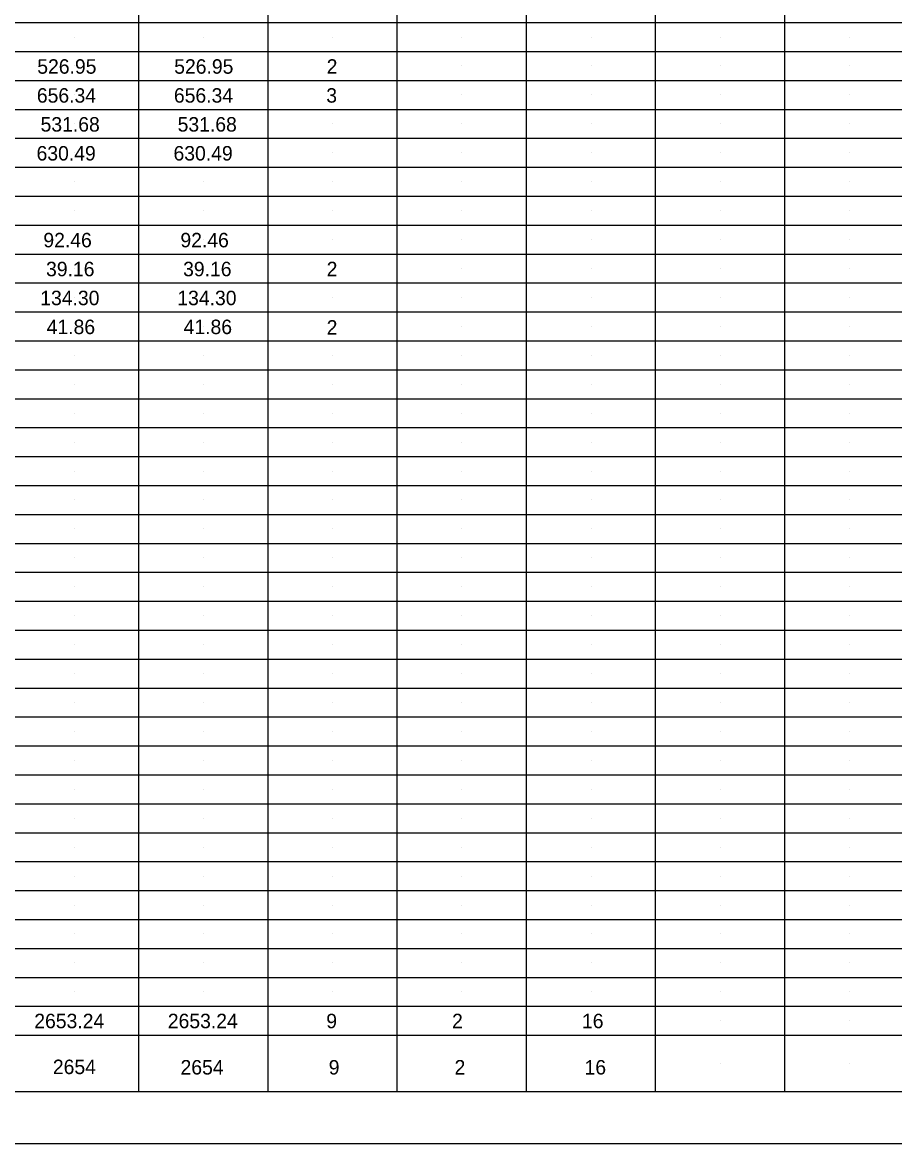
# Model space of a CAD drawing. Extents: x 2073163.9 to 2073197.9, y 634076.5 to 634098.5.
# Drawn here: x 2073181.07 to 2073189.51, y 634076.55 to 634087.4 of the extents above; entities that cross this region are included whole.
import ezdxf

# ---------------------------------------------------------------- set-up
doc = ezdxf.new("R2010")
doc.units = 0
for name, color, linetype in [('SH_Border', 7, 'Continuous'), ('SH_Cut_Line', 7, 'Continuous'), ('SH_Data', 7, 'Continuous'), ('SH_Text', 7, 'Continuous')]:
    doc.layers.add(name, color=color, linetype=linetype)

msp = doc.modelspace()

# ---------------------------------------------------------------- linework, layer by layer
at = {"layer": 'SH_Border'}
msp.add_lwpolyline([(2073165.446, 634098.05), (2073197.446, 634098.05), (2073197.446, 634077.05), (2073165.446, 634077.05)], close=True, dxfattribs=at)
at = {"layer": 'SH_Cut_Line'}
msp.add_lwpolyline([(2073163.946, 634076.55), (2073197.946, 634076.55), (2073197.946, 634098.55), (2073163.946, 634098.55)], close=True, dxfattribs=at)
at = {"layer": 'SH_Data'}
for p, q in [((2073183.446, 634077.05), (2073183.447, 634098.05)), ((2073184.696, 634077.05), (2073184.696, 634098.05)), ((2073187.196, 634077.05), (2073187.196, 634098.05)), ((2073188.446, 634077.05), (2073188.446, 634098.05)), ((2073182.196, 634077.05), (2073182.196, 634097.77)), ((2073185.946, 634077.05), (2073185.946, 634097.77)), ((2073165.446, 634087.398), (2073195.946, 634087.398)), ((2073181.571, 634087.258), (2073181.571, 634087.258)), ((2073182.821, 634087.258), (2073182.821, 634087.258)), ((2073184.071, 634087.258), (2073184.071, 634087.258)), ((2073185.321, 634087.258), (2073185.321, 634087.258)), ((2073186.571, 634087.258), (2073186.571, 634087.258)), ((2073187.821, 634087.258), (2073187.821, 634087.258)), ((2073189.071, 634087.258), (2073189.071, 634087.258)), ((2073165.446, 634087.118), (2073195.946, 634087.118)), ((2073181.571, 634086.978), (2073181.571, 634086.978)), ((2073182.821, 634086.978), (2073182.821, 634086.978)), ((2073184.071, 634086.978), (2073184.071, 634086.978)), ((2073185.321, 634086.978), (2073185.321, 634086.978)), ((2073186.571, 634086.978), (2073186.571, 634086.978)), ((2073187.821, 634086.978), (2073187.821, 634086.978)), ((2073189.071, 634086.978), (2073189.071, 634086.978)), ((2073165.446, 634086.838), (2073195.946, 634086.838)), ((2073181.571, 634086.698), (2073181.571, 634086.698)), ((2073182.821, 634086.698), (2073182.821, 634086.698)), ((2073184.071, 634086.698), (2073184.071, 634086.698)), ((2073185.321, 634086.698), (2073185.321, 634086.698)), ((2073186.571, 634086.698), (2073186.571, 634086.698)), ((2073187.821, 634086.698), (2073187.821, 634086.698)), ((2073189.071, 634086.698), (2073189.071, 634086.698)), ((2073165.446, 634086.558), (2073195.946, 634086.558)), ((2073181.571, 634086.418), (2073181.571, 634086.418)), ((2073182.821, 634086.418), (2073182.821, 634086.418)), ((2073184.071, 634086.418), (2073184.071, 634086.418)), ((2073185.321, 634086.418), (2073185.321, 634086.418)), ((2073186.571, 634086.418), (2073186.571, 634086.418)), ((2073187.821, 634086.418), (2073187.821, 634086.418)), ((2073189.071, 634086.418), (2073189.071, 634086.418)), ((2073165.446, 634086.278), (2073195.946, 634086.278)), ((2073181.571, 634086.138), (2073181.571, 634086.138)), ((2073182.821, 634086.138), (2073182.821, 634086.138)), ((2073184.071, 634086.138), (2073184.071, 634086.138)), ((2073185.321, 634086.138), (2073185.321, 634086.138)), ((2073186.571, 634086.138), (2073186.571, 634086.138)), ((2073187.821, 634086.138), (2073187.821, 634086.138)), ((2073189.071, 634086.138), (2073189.071, 634086.138)), ((2073165.446, 634085.998), (2073195.946, 634085.998)), ((2073181.571, 634085.858), (2073181.571, 634085.858)), ((2073182.821, 634085.858), (2073182.821, 634085.858)), ((2073184.071, 634085.858), (2073184.071, 634085.858)), ((2073185.321, 634085.858), (2073185.321, 634085.858)), ((2073186.571, 634085.858), (2073186.571, 634085.858)), ((2073187.821, 634085.858), (2073187.821, 634085.858)), ((2073189.071, 634085.858), (2073189.071, 634085.858)), ((2073165.446, 634085.718), (2073195.946, 634085.718)), ((2073181.571, 634085.578), (2073181.571, 634085.578)), ((2073182.821, 634085.578), (2073182.821, 634085.578)), ((2073184.071, 634085.578), (2073184.071, 634085.578)), ((2073185.321, 634085.578), (2073185.321, 634085.578)), ((2073186.571, 634085.578), (2073186.571, 634085.578)), ((2073187.821, 634085.578), (2073187.821, 634085.578)), ((2073189.071, 634085.578), (2073189.071, 634085.578)), ((2073165.446, 634085.438), (2073195.946, 634085.438)), ((2073181.571, 634085.298), (2073181.571, 634085.298)), ((2073182.821, 634085.298), (2073182.821, 634085.298)), ((2073184.071, 634085.298), (2073184.071, 634085.298)), ((2073185.321, 634085.298), (2073185.321, 634085.298)), ((2073186.571, 634085.298), (2073186.571, 634085.298)), ((2073187.821, 634085.298), (2073187.821, 634085.298)), ((2073189.071, 634085.298), (2073189.071, 634085.298)), ((2073165.446, 634085.158), (2073195.946, 634085.158)), ((2073181.571, 634085.018), (2073181.571, 634085.018)), ((2073182.821, 634085.018), (2073182.821, 634085.018)), ((2073184.071, 634085.018), (2073184.071, 634085.018)), ((2073185.321, 634085.018), (2073185.321, 634085.018)), ((2073186.571, 634085.018), (2073186.571, 634085.018)), ((2073187.821, 634085.018), (2073187.821, 634085.018)), ((2073189.071, 634085.018), (2073189.071, 634085.018)), ((2073165.446, 634084.878), (2073195.946, 634084.878)), ((2073181.571, 634084.738), (2073181.571, 634084.738)), ((2073182.821, 634084.738), (2073182.821, 634084.738)), ((2073184.071, 634084.738), (2073184.071, 634084.738)), ((2073185.321, 634084.738), (2073185.321, 634084.738)), ((2073186.571, 634084.738), (2073186.571, 634084.738)), ((2073187.821, 634084.738), (2073187.821, 634084.738)), ((2073189.071, 634084.738), (2073189.071, 634084.738)), ((2073165.446, 634084.598), (2073195.946, 634084.598)), ((2073181.571, 634084.458), (2073181.571, 634084.458)), ((2073182.821, 634084.458), (2073182.821, 634084.458)), ((2073184.071, 634084.458), (2073184.071, 634084.458)), ((2073185.321, 634084.458), (2073185.321, 634084.458)), ((2073186.571, 634084.458), (2073186.571, 634084.458)), ((2073187.821, 634084.458), (2073187.821, 634084.458)), ((2073189.071, 634084.458), (2073189.071, 634084.458)), ((2073165.446, 634084.318), (2073195.946, 634084.318)), ((2073181.571, 634084.178), (2073181.571, 634084.178)), ((2073182.821, 634084.178), (2073182.821, 634084.178)), ((2073184.071, 634084.178), (2073184.071, 634084.178)), ((2073185.321, 634084.178), (2073185.321, 634084.178)), ((2073186.571, 634084.178), (2073186.571, 634084.178)), ((2073187.821, 634084.178), (2073187.821, 634084.178)), ((2073189.071, 634084.178), (2073189.071, 634084.178)), ((2073165.446, 634084.038), (2073195.946, 634084.038)), ((2073181.571, 634083.898), (2073181.571, 634083.898)), ((2073182.821, 634083.898), (2073182.821, 634083.898)), ((2073184.071, 634083.898), (2073184.071, 634083.898)), ((2073185.321, 634083.898), (2073185.321, 634083.898)), ((2073186.571, 634083.898), (2073186.571, 634083.898)), ((2073187.821, 634083.898), (2073187.821, 634083.898)), ((2073189.071, 634083.898), (2073189.071, 634083.898)), ((2073165.446, 634083.758), (2073195.946, 634083.758)), ((2073181.571, 634083.618), (2073181.571, 634083.618)), ((2073182.821, 634083.618), (2073182.821, 634083.618)), ((2073184.071, 634083.618), (2073184.071, 634083.618)), ((2073185.321, 634083.618), (2073185.321, 634083.618)), ((2073186.571, 634083.618), (2073186.571, 634083.618)), ((2073187.821, 634083.618), (2073187.821, 634083.618)), ((2073189.071, 634083.618), (2073189.071, 634083.618)), ((2073165.446, 634083.478), (2073195.946, 634083.478)), ((2073181.571, 634083.338), (2073181.571, 634083.338)), ((2073182.821, 634083.338), (2073182.821, 634083.338)), ((2073184.071, 634083.338), (2073184.071, 634083.338)), ((2073185.321, 634083.338), (2073185.321, 634083.338)), ((2073186.571, 634083.338), (2073186.571, 634083.338)), ((2073187.821, 634083.338), (2073187.821, 634083.338)), ((2073189.071, 634083.338), (2073189.071, 634083.338)), ((2073165.446, 634083.198), (2073195.946, 634083.198)), ((2073181.571, 634083.058), (2073181.571, 634083.058)), ((2073182.821, 634083.058), (2073182.821, 634083.058)), ((2073184.071, 634083.058), (2073184.071, 634083.058)), ((2073185.321, 634083.058), (2073185.321, 634083.058)), ((2073186.571, 634083.058), (2073186.571, 634083.058)), ((2073187.821, 634083.058), (2073187.821, 634083.058)), ((2073189.071, 634083.058), (2073189.071, 634083.058)), ((2073165.446, 634082.918), (2073195.946, 634082.918)), ((2073181.571, 634082.778), (2073181.571, 634082.778)), ((2073182.821, 634082.778), (2073182.821, 634082.778)), ((2073184.071, 634082.778), (2073184.071, 634082.778)), ((2073185.321, 634082.778), (2073185.321, 634082.778)), ((2073186.571, 634082.778), (2073186.571, 634082.778)), ((2073187.821, 634082.778), (2073187.821, 634082.778)), ((2073189.071, 634082.778), (2073189.071, 634082.778)), ((2073165.446, 634082.638), (2073195.946, 634082.638)), ((2073181.571, 634082.498), (2073181.571, 634082.498)), ((2073182.821, 634082.498), (2073182.821, 634082.498)), ((2073184.071, 634082.498), (2073184.071, 634082.498)), ((2073185.321, 634082.498), (2073185.321, 634082.498)), ((2073186.571, 634082.498), (2073186.571, 634082.498)), ((2073187.821, 634082.498), (2073187.821, 634082.498)), ((2073189.071, 634082.498), (2073189.071, 634082.498)), ((2073165.446, 634082.358), (2073195.946, 634082.358)), ((2073181.571, 634082.218), (2073181.571, 634082.218)), ((2073182.821, 634082.218), (2073182.821, 634082.218)), ((2073184.071, 634082.218), (2073184.071, 634082.218)), ((2073185.321, 634082.218), (2073185.321, 634082.218)), ((2073186.571, 634082.218), (2073186.571, 634082.218)), ((2073187.821, 634082.218), (2073187.821, 634082.218)), ((2073189.071, 634082.218), (2073189.071, 634082.218)), ((2073165.446, 634082.078), (2073195.946, 634082.078)), ((2073181.571, 634081.938), (2073181.571, 634081.938)), ((2073182.821, 634081.938), (2073182.821, 634081.938)), ((2073184.071, 634081.938), (2073184.071, 634081.938)), ((2073185.321, 634081.938), (2073185.321, 634081.938)), ((2073186.571, 634081.938), (2073186.571, 634081.938)), ((2073187.821, 634081.938), (2073187.821, 634081.938)), ((2073189.071, 634081.938), (2073189.071, 634081.938)), ((2073165.446, 634081.798), (2073195.946, 634081.798)), ((2073181.571, 634081.658), (2073181.571, 634081.658)), ((2073182.821, 634081.658), (2073182.821, 634081.658)), ((2073184.071, 634081.658), (2073184.071, 634081.658)), ((2073185.321, 634081.658), (2073185.321, 634081.658)), ((2073186.571, 634081.658), (2073186.571, 634081.658)), ((2073187.821, 634081.658), (2073187.821, 634081.658)), ((2073189.071, 634081.658), (2073189.071, 634081.658)), ((2073165.446, 634081.518), (2073195.946, 634081.518)), ((2073181.571, 634081.378), (2073181.571, 634081.378)), ((2073182.821, 634081.378), (2073182.821, 634081.378)), ((2073184.071, 634081.378), (2073184.071, 634081.378)), ((2073185.321, 634081.378), (2073185.321, 634081.378)), ((2073186.571, 634081.378), (2073186.571, 634081.378)), ((2073187.821, 634081.378), (2073187.821, 634081.378)), ((2073189.071, 634081.378), (2073189.071, 634081.378)), ((2073165.446, 634081.238), (2073195.946, 634081.238)), ((2073181.571, 634081.098), (2073181.571, 634081.098)), ((2073182.821, 634081.098), (2073182.821, 634081.098)), ((2073184.071, 634081.098), (2073184.071, 634081.098)), ((2073185.321, 634081.098), (2073185.321, 634081.098)), ((2073186.571, 634081.098), (2073186.571, 634081.098)), ((2073187.821, 634081.098), (2073187.821, 634081.098)), ((2073189.071, 634081.098), (2073189.071, 634081.098)), ((2073165.446, 634080.958), (2073195.946, 634080.958)), ((2073181.571, 634080.818), (2073181.571, 634080.818)), ((2073182.821, 634080.818), (2073182.821, 634080.818)), ((2073184.071, 634080.818), (2073184.071, 634080.818)), ((2073185.321, 634080.818), (2073185.321, 634080.818)), ((2073186.571, 634080.818), (2073186.571, 634080.818)), ((2073187.821, 634080.818), (2073187.821, 634080.818)), ((2073189.071, 634080.818), (2073189.071, 634080.818)), ((2073165.446, 634080.678), (2073195.946, 634080.678)), ((2073181.571, 634080.538), (2073181.571, 634080.538)), ((2073182.821, 634080.538), (2073182.821, 634080.538)), ((2073184.071, 634080.538), (2073184.071, 634080.538)), ((2073185.321, 634080.538), (2073185.321, 634080.538)), ((2073186.571, 634080.538), (2073186.571, 634080.538)), ((2073187.821, 634080.538), (2073187.821, 634080.538)), ((2073189.071, 634080.538), (2073189.071, 634080.538)), ((2073165.446, 634080.398), (2073195.946, 634080.398)), ((2073181.571, 634080.258), (2073181.571, 634080.258)), ((2073182.821, 634080.258), (2073182.821, 634080.258)), ((2073184.071, 634080.258), (2073184.071, 634080.258)), ((2073185.321, 634080.258), (2073185.321, 634080.258)), ((2073186.571, 634080.258), (2073186.571, 634080.258)), ((2073187.821, 634080.258), (2073187.821, 634080.258)), ((2073189.071, 634080.258), (2073189.071, 634080.258)), ((2073165.446, 634080.118), (2073195.946, 634080.118)), ((2073181.571, 634079.978), (2073181.571, 634079.978)), ((2073182.821, 634079.978), (2073182.821, 634079.978)), ((2073184.071, 634079.978), (2073184.071, 634079.978)), ((2073185.321, 634079.978), (2073185.321, 634079.978)), ((2073186.571, 634079.978), (2073186.571, 634079.978)), ((2073187.821, 634079.978), (2073187.821, 634079.978)), ((2073189.071, 634079.978), (2073189.071, 634079.978)), ((2073165.446, 634079.838), (2073195.946, 634079.838)), ((2073181.571, 634079.698), (2073181.571, 634079.698)), ((2073182.821, 634079.698), (2073182.821, 634079.698)), ((2073184.071, 634079.698), (2073184.071, 634079.698)), ((2073185.321, 634079.698), (2073185.321, 634079.698)), ((2073186.571, 634079.698), (2073186.571, 634079.698)), ((2073187.821, 634079.698), (2073187.821, 634079.698)), ((2073189.071, 634079.698), (2073189.071, 634079.698)), ((2073165.446, 634079.558), (2073195.946, 634079.558)), ((2073181.571, 634079.418), (2073181.571, 634079.418)), ((2073182.821, 634079.418), (2073182.821, 634079.418)), ((2073184.071, 634079.418), (2073184.071, 634079.418)), ((2073185.321, 634079.418), (2073185.321, 634079.418)), ((2073186.571, 634079.418), (2073186.571, 634079.418)), ((2073187.821, 634079.418), (2073187.821, 634079.418)), ((2073189.071, 634079.418), (2073189.071, 634079.418)), ((2073165.446, 634079.278), (2073195.946, 634079.278)), ((2073181.571, 634079.138), (2073181.571, 634079.138)), ((2073182.821, 634079.138), (2073182.821, 634079.138)), ((2073184.071, 634079.138), (2073184.071, 634079.138)), ((2073185.321, 634079.138), (2073185.321, 634079.138)), ((2073186.571, 634079.138), (2073186.571, 634079.138)), ((2073187.821, 634079.138), (2073187.821, 634079.138)), ((2073189.071, 634079.138), (2073189.071, 634079.138)), ((2073165.446, 634078.998), (2073195.946, 634078.998)), ((2073181.571, 634078.858), (2073181.571, 634078.858)), ((2073182.821, 634078.858), (2073182.821, 634078.858)), ((2073184.071, 634078.858), (2073184.071, 634078.858)), ((2073185.321, 634078.858), (2073185.321, 634078.858)), ((2073186.571, 634078.858), (2073186.571, 634078.858)), ((2073187.821, 634078.858), (2073187.821, 634078.858)), ((2073189.071, 634078.858), (2073189.071, 634078.858)), ((2073165.446, 634078.718), (2073195.946, 634078.718)), ((2073181.571, 634078.578), (2073181.571, 634078.578)), ((2073182.821, 634078.578), (2073182.821, 634078.578)), ((2073184.071, 634078.578), (2073184.071, 634078.578)), ((2073185.321, 634078.578), (2073185.321, 634078.578)), ((2073186.571, 634078.578), (2073186.571, 634078.578)), ((2073187.821, 634078.578), (2073187.821, 634078.578)), ((2073189.071, 634078.578), (2073189.071, 634078.578)), ((2073165.446, 634078.438), (2073195.946, 634078.438)), ((2073181.571, 634078.298), (2073181.571, 634078.298)), ((2073182.821, 634078.298), (2073182.821, 634078.298)), ((2073184.071, 634078.298), (2073184.071, 634078.298)), ((2073185.321, 634078.298), (2073185.321, 634078.298)), ((2073186.571, 634078.298), (2073186.571, 634078.298)), ((2073187.821, 634078.298), (2073187.821, 634078.298)), ((2073189.071, 634078.298), (2073189.071, 634078.298)), ((2073165.446, 634078.158), (2073195.946, 634078.158)), ((2073181.571, 634078.018), (2073181.571, 634078.018)), ((2073182.821, 634078.018), (2073182.821, 634078.018)), ((2073184.071, 634078.018), (2073184.071, 634078.018)), ((2073185.321, 634078.018), (2073185.321, 634078.018)), ((2073186.571, 634078.018), (2073186.571, 634078.018)), ((2073187.821, 634078.018), (2073187.821, 634078.018)), ((2073189.071, 634078.018), (2073189.071, 634078.018)), ((2073165.446, 634077.878), (2073195.946, 634077.878)), ((2073181.571, 634077.738), (2073181.571, 634077.738)), ((2073182.821, 634077.738), (2073182.821, 634077.738)), ((2073184.071, 634077.738), (2073184.071, 634077.738)), ((2073185.321, 634077.738), (2073185.321, 634077.738)), ((2073186.571, 634077.738), (2073186.571, 634077.738)), ((2073187.821, 634077.738), (2073187.821, 634077.738)), ((2073189.071, 634077.738), (2073189.071, 634077.738)), ((2073165.446, 634077.598), (2073195.946, 634077.598)), ((2073181.571, 634077.324), (2073181.571, 634077.324)), ((2073182.821, 634077.324), (2073182.821, 634077.324)), ((2073184.071, 634077.324), (2073184.071, 634077.324)), ((2073185.321, 634077.324), (2073185.321, 634077.324)), ((2073186.571, 634077.324), (2073186.571, 634077.324)), ((2073187.821, 634077.324), (2073187.821, 634077.324)), ((2073189.071, 634077.324), (2073189.071, 634077.324))]:
    msp.add_line(p, q, dxfattribs=at)

# ---------------------------------------------------------------- texts
at = {"layer": 'SH_Text'}
for s, p in [('526.95', (2073181.213, 634086.903)), ('526.95', (2073182.538, 634086.903)), ('2', (2073184.013, 634086.903)), ('656.34', (2073181.209, 634086.623)), ('656.34', (2073182.535, 634086.623)), ('3', (2073184.009, 634086.623)), ('531.68', (2073181.245, 634086.343)), ('531.68', (2073182.571, 634086.343)), ('630.49', (2073181.206, 634086.063)), ('630.49', (2073182.531, 634086.063)), ('92.46', (2073181.272, 634085.223)), ('92.46', (2073182.598, 634085.223)), ('39.16', (2073181.298, 634084.943)), ('39.16', (2073182.624, 634084.943)), ('2', (2073184.013, 634084.943)), ('134.30', (2073181.242, 634084.663)), ('134.30', (2073182.568, 634084.663)), ('41.86', (2073181.304, 634084.383)), ('41.86', (2073182.629, 634084.383)), ('2', (2073184.013, 634084.378)), ('2653.24', (2073181.184, 634077.666)), ('2653.24', (2073182.476, 634077.666)), ('9', (2073184.009, 634077.666)), ('2', (2073185.226, 634077.666)), ('16', (2073186.483, 634077.666)), ('2654', (2073181.364, 634077.222)), ('2654', (2073182.599, 634077.218)), ('9', (2073184.033, 634077.218)), ('2', (2073185.25, 634077.218)), ('16', (2073186.508, 634077.218))]:
    msp.add_text(s, height=0.14, rotation=0.0001, dxfattribs=at).set_placement(p)

doc.saveas('drawing.dxf')
